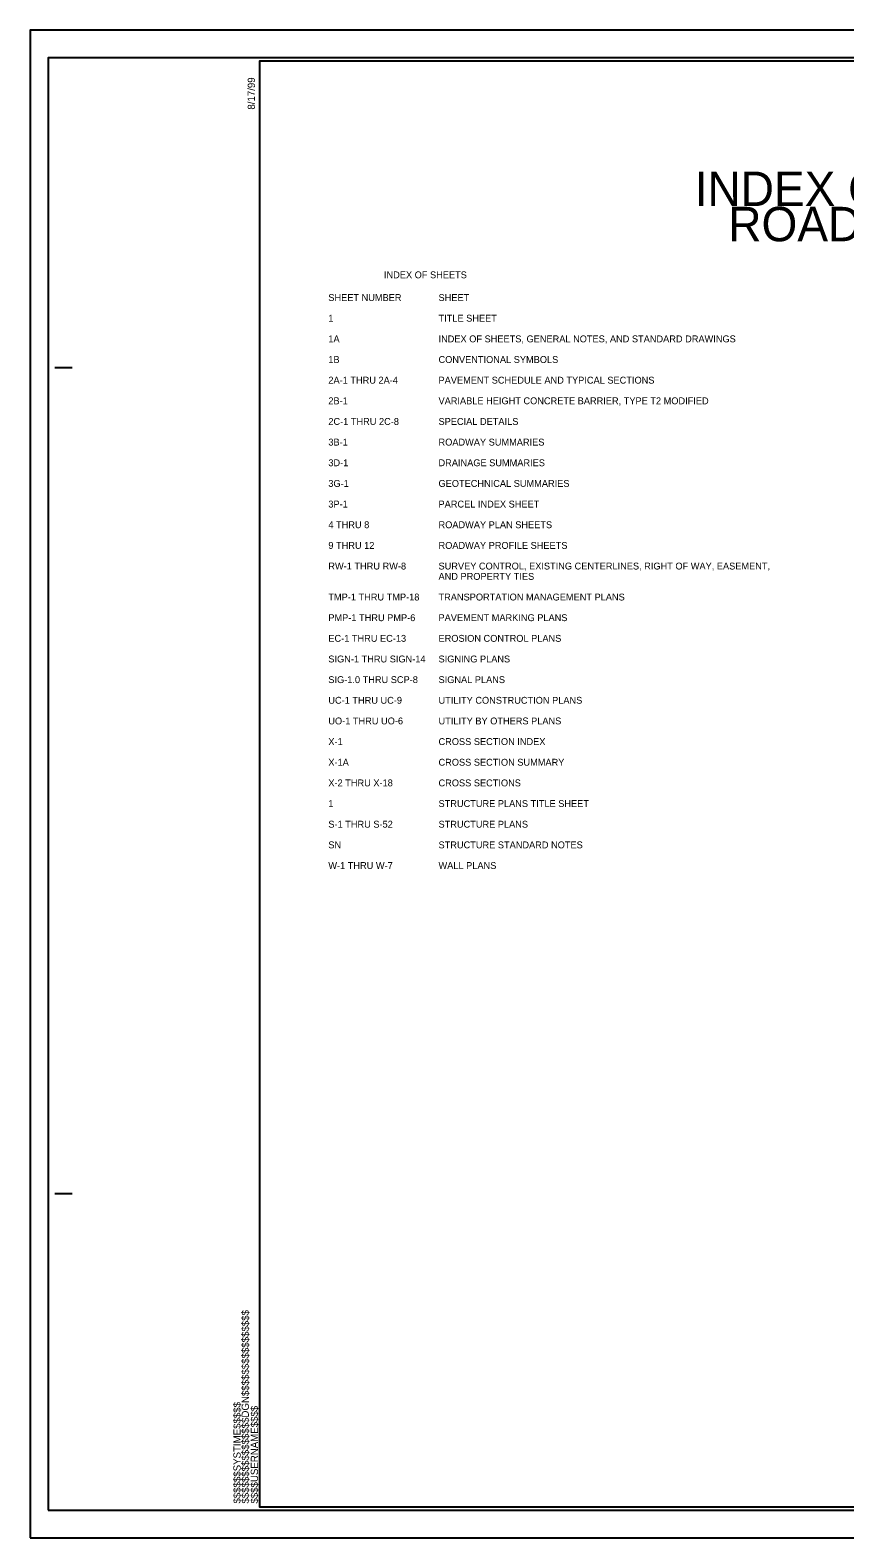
# Model space of a CAD drawing. Extents: x 775818 to 777502, y 889228 to 890323.
# Drawn here: x 775818 to 776410, y 889228 to 890323 of the extents above; entities that cross this region are included whole.
import ezdxf

# ---------------------------------------------------------------- set-up
doc = ezdxf.new("R2010")
doc.units = 0
for name, color, linetype in [('Sheet Cutting Line CELL', 7, 'Continuous'), ('Sheet Data Field CELL', 7, 'Continuous'), ('Sheet Data Text CELL', 7, 'Continuous'), ('Sheet Plan CELL', 7, 'Continuous'), ('Sheet Plot Border Inside CELL', 7, 'Continuous'), ('Sheet Plot Border Outside CELL', 7, 'Continuous')]:
    doc.layers.add(name, color=color, linetype=linetype)

msp = doc.modelspace()

# ---------------------------------------------------------------- linework, layer by layer
at = {"layer": 'Sheet Cutting Line CELL'}
for p, q in [((777501.8, 890323.3), (775818.3, 890323.3)), ((775818.3, 890323.3), (775818.3, 889228.3)), ((775818.3, 889228.3), (777501.8, 889228.3))]:
    msp.add_line(p, q, dxfattribs=at)
at = {"layer": 'Sheet Plan CELL'}
for p, q in [((775984.8, 890300.8), (775984.8, 890300.8)), ((775836.3, 890078.3), (775848.8, 890078.3)), ((775836.3, 889478.3), (775848.8, 889478.3)), ((775984.8, 889250.8), (775984.8, 889250.8))]:
    msp.add_line(p, q, dxfattribs=at)
msp.add_lwpolyline([(777484.8, 890300.8), (775984.8, 890300.8), (775984.8, 889250.8), (777484.8, 889250.8)], close=True, dxfattribs=at)
at = {"layer": 'Sheet Plot Border Inside CELL'}
msp.add_lwpolyline([(775831.3, 889248.3), (777497.3, 889248.3), (777497.3, 890303.3), (775831.3, 890303.3)], close=True, dxfattribs=at)
at = {"layer": 'Sheet Plot Border Outside CELL'}
msp.add_lwpolyline([(775818.3, 889228.3), (777501.8, 889228.3), (777501.8, 890323.3), (775818.3, 890323.3)], close=True, dxfattribs=at)

# ---------------------------------------------------------------- texts
at = {"layer": 'Sheet Data Field CELL'}
for s, p in [('INDEX OF SHEETS, GENERAL NOTES AND 2024 ', (776300.8, 890195.6)), ('ROADWAY ENGLISH STANDARD DRAWINGS', (776325.2, 890170))]:
    msp.add_text(s, height=25, dxfattribs=at).set_placement(p)
at = {"layer": 'Sheet Data Text CELL'}
msp.add_text('INDEX OF SHEETS', height=5, rotation=360, dxfattribs=at).set_placement((776075.2, 890143.1))
for s, p in [('SHEET NUMBER', (776034.8, 890126.6)), ('SHEET', (776114.8, 890126.6)), ('1', (776034.8, 890111.6)), ('TITLE SHEET', (776114.8, 890111.6)), ('1A', (776034.8, 890096.6)), ('INDEX OF SHEETS, GENERAL NOTES, AND STANDARD DRAWINGS', (776114.8, 890096.6)), ('1B', (776034.8, 890081.6)), ('CONVENTIONAL SYMBOLS', (776114.8, 890081.6)), ('2A-1 THRU 2A-4', (776034.8, 890066.6)), ('PAVEMENT SCHEDULE AND TYPICAL SECTIONS', (776114.8, 890066.6)), ('2B-1', (776034.8, 890051.6)), ('VARIABLE HEIGHT CONCRETE BARRIER, TYPE T2 MODIFIED', (776114.8, 890051.6)), ('2C-1 THRU 2C-8', (776034.8, 890036.6)), ('SPECIAL DETAILS', (776114.8, 890036.6)), ('3B-1', (776034.8, 890021.6)), ('ROADWAY SUMMARIES', (776114.8, 890021.6)), ('3D-1', (776034.8, 890006.6)), ('DRAINAGE SUMMARIES', (776114.8, 890006.6)), ('3G-1', (776034.8, 889991.6)), ('GEOTECHNICAL SUMMARIES', (776114.8, 889991.6)), ('3P-1', (776034.8, 889976.6)), ('PARCEL INDEX SHEET', (776114.8, 889976.6)), ('4 THRU 8', (776034.8, 889961.6)), ('ROADWAY PLAN SHEETS', (776114.8, 889961.6)), ('9 THRU 12', (776034.8, 889946.6)), ('ROADWAY PROFILE SHEETS', (776114.8, 889946.6)), ('RW-1 THRU RW-8', (776034.8, 889931.6)), ('AND PROPERTY TIES', (776114.8, 889924.1)), ('SURVEY CONTROL, EXISTING CENTERLINES, RIGHT OF WAY, EASEMENT,', (776114.8, 889931.6)), ('TMP-1 THRU TMP-18', (776034.8, 889909.1)), ('TRANSPORTATION MANAGEMENT PLANS', (776114.8, 889909.1)), ('PMP-1 THRU PMP-6', (776034.8, 889894.1)), ('PAVEMENT MARKING PLANS', (776114.8, 889894.1)), ('EC-1 THRU EC-13', (776034.8, 889879.1)), ('EROSION CONTROL PLANS', (776114.8, 889879.1)), ('SIGN-1 THRU SIGN-14', (776034.8, 889864.1)), ('SIGNING PLANS', (776114.8, 889864.1)), ('SIG-1.0 THRU SCP-8', (776034.8, 889849.1)), ('SIGNAL PLANS', (776114.8, 889849.1)), ('UC-1 THRU UC-9', (776034.8, 889834.1)), ('UTILITY CONSTRUCTION PLANS', (776114.8, 889834.1)), ('UO-1 THRU UO-6', (776034.8, 889819.1)), ('UTILITY BY OTHERS PLANS', (776114.8, 889819.1)), ('X-1', (776034.8, 889804.1)), ('CROSS SECTION INDEX', (776114.8, 889804.1)), ('X-1A', (776034.8, 889789.1)), ('CROSS SECTION SUMMARY', (776114.8, 889789.1)), ('X-2 THRU X-18', (776034.8, 889774.1)), ('CROSS SECTIONS', (776114.8, 889774.1)), ('1', (776034.8, 889759.1)), ('STRUCTURE PLANS TITLE SHEET', (776114.8, 889759.1)), ('S-1 THRU S-52', (776034.8, 889744.1)), ('STRUCTURE PLANS', (776114.8, 889744.1)), ('SN', (776034.8, 889729.1)), ('STRUCTURE STANDARD NOTES', (776114.8, 889729.1)), ('W-1 THRU W-7', (776034.8, 889714.1)), ('WALL PLANS', (776114.8, 889714.1))]:
    msp.add_text(s, height=5, dxfattribs=at).set_placement(p)
at = {"layer": 'Sheet Plan CELL'}
for s, p in [('8/17/99', (775981.5, 890265.6)), ('$$$$$$$$$$$$$$$$DGN$$$$$$$$$$$$$$$$', (775977.1, 889253.2)), ('$$$$$$SYSTIME$$$$$', (775971.1, 889253.2)), ('$$$$USERNAME$$$$', (775983.7, 889253.2))]:
    msp.add_text(s, height=5.25, rotation=90, dxfattribs=at).set_placement(p)

doc.saveas('drawing.dxf')
